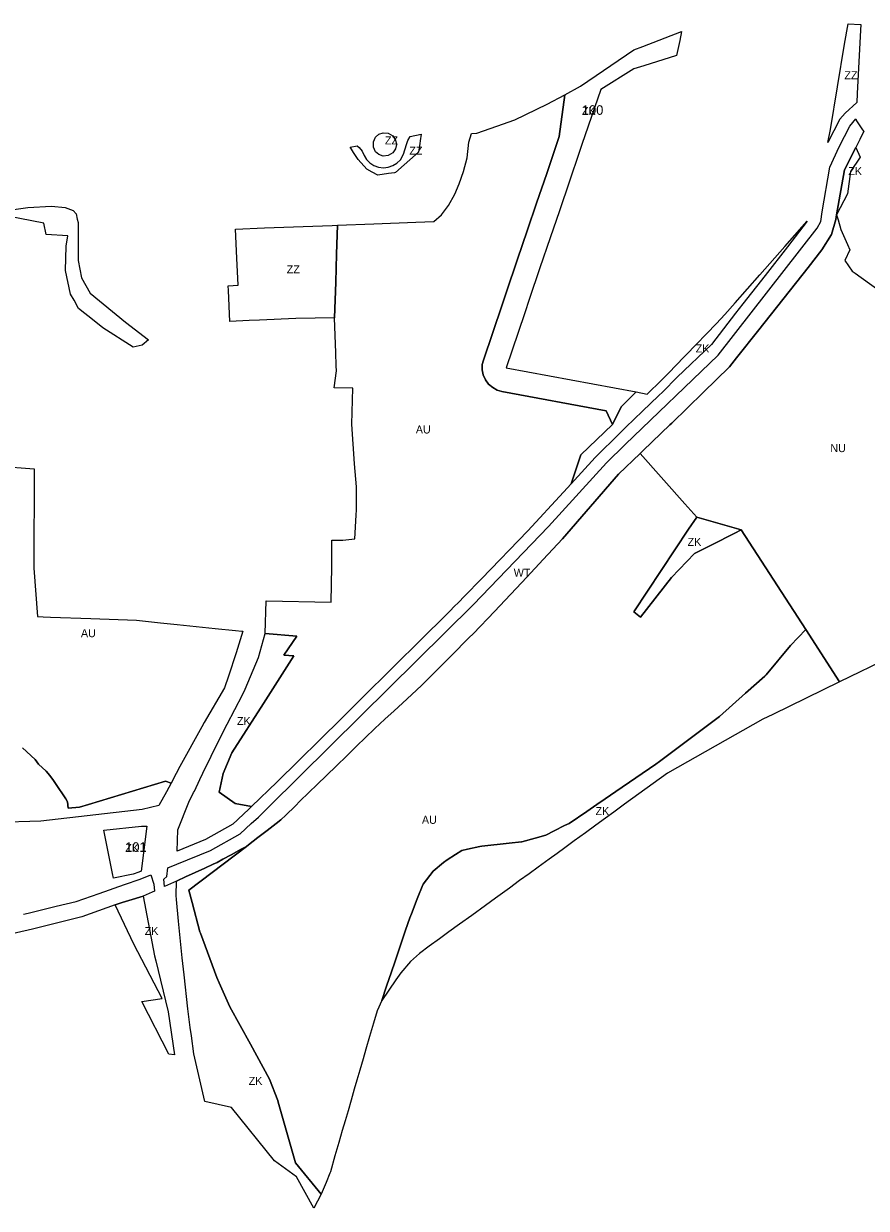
# Model space of a CAD drawing. Extents: x -535894 to -532834, y -1165802 to -1163647.
# Drawn here: x -534347 to -533821, y -1165557 to -1164817 of the extents above; entities that cross this region are included whole.
import ezdxf

# ---------------------------------------------------------------- set-up
doc = ezdxf.new("R2010")
doc.units = 0
for name, color, linetype in [('Vrstva 10', 7, 'Continuous'), ('Vrstva 16', 7, 'Continuous'), ('Vrstva 17', 7, 'Continuous'), ('Vrstva 19', 7, 'Continuous'), ('Vrstva 22', 7, 'Continuous'), ('Vrstva 4', 7, 'Continuous'), ('Vrstva 61', 7, 'Continuous')]:
    doc.layers.add(name, color=color, linetype=linetype)

msp = doc.modelspace()

# ---------------------------------------------------------------- linework, layer by layer
at = {"layer": 'Vrstva 10'}
for points in [[(-533843.57, -1164882.92), (-533834.83, -1164829.61), (-533832.622, -1164816.867), (-533824.861, -1164817.398), (-533824.726, -1164817.407), (-533824.567, -1164817.419), (-533824.9, -1164820.82), (-533826.93, -1164860.55), (-533827.206, -1164866.027), (-533834.51, -1164872.77), (-533837.807, -1164876.568), (-533845.178, -1164891.097)], [(-534119.58, -1164910.55), (-534126.18, -1164911.51), (-534129.86, -1164909.55), (-534133.17, -1164907.78), (-534138.57, -1164901.68), (-534141.45, -1164897.26), (-534142.74, -1164895.29), (-534143.59, -1164893.98), (-534139.15, -1164893.18), (-534137.85, -1164894.21), (-534136.17, -1164896.41), (-534136.05, -1164896.57), (-534134.79, -1164899.23), (-534133.26, -1164901.76), (-534131.19, -1164903.88), (-534128.69, -1164905.48), (-534125.82, -1164906.5), (-534122.74, -1164906.88), (-534119.83, -1164906.52), (-534117.01, -1164905.53), (-534114.35, -1164903.98), (-534112.2, -1164901.85), (-534110.31, -1164898.33), (-534108.42, -1164892.42), (-534108.18, -1164891.67), (-534107.59, -1164889.81), (-534106.11, -1164887.27), (-534099.32, -1164885.91), (-534099.92, -1164890.03), (-534100.15, -1164891.69), (-534100.95, -1164897.17), (-534115.28, -1164909.92), (-534115.91, -1164910.01)], [(-534129.089, -1164891.38), (-534129.089, -1164890.617), (-534127.712, -1164887.754), (-534125.618, -1164885.941), (-534123.001, -1164885.034), (-534119.833, -1164885.273), (-534116.941, -1164886.943), (-534115.564, -1164888.961), (-534115.15, -1164889.567), (-534114.627, -1164892.287), (-534115.15, -1164895.006), (-534116.941, -1164897.631), (-534119.833, -1164899.301), (-534123.001, -1164899.539), (-534125.618, -1164898.633), (-534127.712, -1164896.82), (-534129.089, -1164893.957)], [(-534151.409, -1164942.758), (-534151.409, -1164942.758), (-534152.01, -1164960.841), (-534152.589, -1164978.252), (-534153.33, -1165000.55), (-534177.53, -1165001), (-534200.18, -1165002.04), (-534206.706, -1165002.339), (-534218.76, -1165002.89), (-534219.6, -1164983.53), (-534219.73, -1164980.58), (-534213.51, -1164980.26), (-534214.43, -1164963.28), (-534215.272, -1164945.309), (-534197.15, -1164944.46), (-534154.72, -1164942.88)]]:
    msp.add_lwpolyline(points, close=True, dxfattribs=at)
msp.add_lwpolyline([(-534369.994, -1164935.234), (-534344.906, -1164931.755), (-534330.148, -1164930.912), (-534321.609, -1164931.634), (-534316.655, -1164933.547), (-534314.652, -1164935.656), (-534313.98, -1164938.937), (-534313.54, -1164941.084), (-534313.54, -1164953.57), (-534313.47, -1164964.73), (-534311.34, -1164975.55), (-534305.86, -1164985.22), (-534283.92, -1165003.31), (-534269.44, -1165014.34), (-534273.424, -1165017.68), (-534279.05, -1165019.05), (-534298, -1165006.84), (-534305.55, -1165000.89), (-534309.23, -1164997.99), (-534313.18, -1164994.87), (-534316.03, -1164989.68), (-534318.16, -1164985.83), (-534321.41, -1164971.12), (-534320.97, -1164955.95), (-534319.84, -1164949.47), (-534333.48, -1164948.48), (-534334.97, -1164941.39), (-534357.43, -1164937.18)], dxfattribs=at)
at = {"layer": 'Vrstva 16'}
for points in [[(-533834.91, -1164908.26), (-533827.81, -1164894.29), (-533825.11, -1164900.3), (-533831.01, -1164909.18), (-533832.91, -1164923.14), (-533839.74, -1164936.26)], [(-533990.612, -1165087.806), (-534005.544, -1165104.269), (-533999.48, -1165086.16), (-533979.67, -1165067.29), (-533974.3, -1165056.33), (-533964.89, -1165046.93), (-533958, -1165048.21), (-533949.192, -1165039.528), (-533943.27, -1165033.69), (-533941.12, -1165031.45), (-533933.76, -1165023.78), (-533914.87, -1165004.11), (-533909.61, -1164998.62), (-533903.09, -1164991.22), (-533887.6, -1164973.66), (-533872.1, -1164956.08), (-533858.16, -1164940.26), (-533870.466, -1164956.339), (-533884.317, -1164974.086), (-533898.225, -1164991.906), (-533902.835, -1164997.813), (-533917.983, -1165017.223), (-533939.32, -1165037.78), (-533948.251, -1165046.797), (-533950.892, -1165049.339), (-533960.954, -1165059.022), (-533971.32, -1165068.999), (-533974.832, -1165072.379)], [(-533899.27, -1165133.08), (-533903.4, -1165135.17), (-533917.7, -1165142.45), (-533922.67, -1165144.99), (-533928.42, -1165147.92), (-533942.82, -1165162.9), (-533962.19, -1165187.57), (-533966.39, -1165184.39), (-533932.156, -1165132.628), (-533927.15, -1165125.06)], [(-534251.577, -1165333.784), (-534251.27, -1165320.44), (-534244.31, -1165303.28), (-534241.33, -1165297.17), (-534240.88, -1165296.25), (-534237.36, -1165289.01), (-534235.49, -1165285.14), (-534225.18, -1165263.79), (-534220.39, -1165254.46), (-534210.89, -1165236.07), (-534209.06, -1165232.51), (-534200.78, -1165212.83), (-534196.74, -1165197.75), (-534176.94, -1165199.42), (-534185.07, -1165211.45), (-534178.75, -1165211.76), (-534197.75, -1165241.47), (-534217.42, -1165272.37), (-534222.91, -1165285.36), (-534225.42, -1165296.87), (-534215.31, -1165304.06), (-534205.1, -1165305.987), (-534206.827, -1165307.611), (-534213.437, -1165313.824), (-534213.981, -1165314.335), (-534216.742, -1165316.93), (-534233.955, -1165326.611)], [(-533837.937, -1165228.09), (-533879.59, -1165248.35), (-533885.93, -1165251.42), (-533945.33, -1165285.03), (-533972.2, -1165304.55), (-533978.9, -1165309.42), (-533984.1, -1165313.19), (-533990.15, -1165317.59), (-533996.63, -1165322.3), (-534003.61, -1165327.37), (-534009.54, -1165331.68), (-534014.32, -1165335.17), (-534019.31, -1165338.8), (-534026.18, -1165343.78), (-534031.82, -1165347.88), (-534037.71, -1165352.16), (-534044.14, -1165356.83), (-534052.73, -1165363.08), (-534059.04, -1165367.66), (-534067.65, -1165373.91), (-534075.22, -1165379.41), (-534081.89, -1165384.25), (-534087.82, -1165388.56), (-534094.23, -1165393.22), (-534100.32, -1165397.66), (-534105.93, -1165402.64), (-534112, -1165409.73), (-534115, -1165414.12), (-534119.41, -1165420.59), (-534123.86, -1165427.13), (-534120.771, -1165418.057), (-534117.758, -1165409.211), (-534115.724, -1165403.237), (-534111.863, -1165391.898), (-534108.906, -1165383.215), (-534106.3, -1165375.56), (-534105.277, -1165372.936), (-534101.626, -1165363.573), (-534098.22, -1165354.84), (-534097.973, -1165354.516), (-534091.65, -1165346.25), (-534085.262, -1165340.992), (-534083.06, -1165339.18), (-534077.737, -1165335.863), (-534073.72, -1165333.36), (-534070.381, -1165332.603), (-534062.61, -1165330.84), (-534061.335, -1165330.704), (-534044.246, -1165328.878), (-534036.59, -1165328.06), (-534036.334, -1165327.987), (-534027.934, -1165325.603), (-534021.44, -1165323.76), (-534016.244, -1165321.16), (-534009.645, -1165317.859), (-534006.79, -1165316.43), (-533995.833, -1165308.952), (-533989.599, -1165304.697), (-533984.271, -1165301.06), (-533977.619, -1165296.52), (-533952.74, -1165279.54), (-533950.278, -1165277.701), (-533912.83, -1165249.72), (-533896.579, -1165235.159), (-533884.619, -1165224.443), (-533883.79, -1165223.7), (-533868.63, -1165205.25), (-533859.04, -1165195.4)], [(-534240.38, -1165347.14), (-534234.4, -1165344.4), (-534229.05, -1165341.96), (-534226.73, -1165340.9), (-534223, -1165338.87), (-534217.81, -1165336.04), (-534211.58, -1165332.65), (-534208.23, -1165330.82), (-534244.32, -1165358.176), (-534242.299, -1165365.808), (-534237.43, -1165384.2), (-534237.131, -1165385.002), (-534226.8, -1165412.68), (-534225.304, -1165416.084), (-534218.71, -1165431.09), (-534205.89, -1165454.365), (-534193.89, -1165476.15), (-534188.83, -1165489.57), (-534188.526, -1165490.638), (-534177.746, -1165528.448), (-534161.64, -1165548.15), (-534166.28, -1165556.93), (-534177.14, -1165537.32), (-534190.83, -1165527.2), (-534217.59, -1165493.98), (-534234.3, -1165490.14), (-534241.22, -1165460.36), (-534242.7, -1165449.22), (-534243.4, -1165444.03), (-534244.98, -1165432.27), (-534247.31, -1165411.07), (-534248.48, -1165400.41), (-534250.69, -1165377.47), (-534251.99, -1165363.99), (-534252.23, -1165361.54), (-534252.01, -1165352.47), (-534251.58, -1165352.26), (-534246.5, -1165349.94)], [(-534281.74, -1165364.67), (-534272.9, -1165362.02), (-534265.72, -1165399.2), (-534264.94, -1165402.42), (-534262.04, -1165414.36), (-534257.19, -1165434.29), (-534253.34, -1165461.15), (-534256.73, -1165460.61), (-534273.58, -1165427.79), (-534260.88, -1165425.85), (-534278.69, -1165391.9), (-534290.38, -1165367.27), (-534285.88, -1165365.91)]]:
    msp.add_lwpolyline(points, close=True, dxfattribs=at)
msp.add_lwpolyline([(-534348.28, -1165269.23), (-534340.36, -1165276.59), (-534338.28, -1165279.56), (-534333.44, -1165283.8), (-534331.16, -1165286.47), (-534328.82, -1165289.63), (-534326.29, -1165293.35), (-534322.34, -1165299.19), (-534321.2, -1165301.18), (-534320.19, -1165302.94), (-534319.78, -1165307.01), (-534312.62, -1165306.37), (-534306.94, -1165304.65), (-534258.88, -1165290.11), (-534255.45, -1165291.38), (-534258.18, -1165296.74), (-534263.07, -1165305.2), (-534273.43, -1165307.68), (-534336.76, -1165315.12), (-534364.57, -1165315.97)], dxfattribs=at)
at = {"layer": 'Vrstva 17'}
for points in [[(-533960.78, -1164831.03), (-533936.53, -1164821.76), (-533937.75, -1164827.32), (-533939.824, -1164836.771), (-533960.22, -1164843.182), (-533966.45, -1164845.14), (-533986.98, -1164857.88), (-533998.79, -1164892.25), (-534000.56, -1164897.43), (-534006.6, -1164915.2), (-534012.88, -1164933.73), (-534018.61, -1164950.58), (-534025.02, -1164969.45), (-534031.7, -1164989.14), (-534034.52, -1164997.43), (-534038.74, -1165009.878), (-534046.172, -1165031.796), (-533964.89, -1165046.93), (-533974.3, -1165056.33), (-533979.67, -1165067.29), (-533983.719, -1165058.682), (-534048.917, -1165046.543), (-534051.748, -1165045.721), (-534054.541, -1165044.245), (-534057.072, -1165042.101), (-534059.114, -1165039.378), (-534060.49, -1165036.266), (-534061.122, -1165033.009), (-534061.045, -1165029.851), (-534060.377, -1165026.98), (-534048.723, -1164992.607), (-534045.903, -1164984.315), (-534039.224, -1164964.628), (-534032.812, -1164945.753), (-534027.084, -1164928.908), (-534020.803, -1164910.376), (-534012.983, -1164887.396), (-534009.46, -1164861.214), (-533999.79, -1164855.92), (-533966.36, -1164833.16)], [(-534274.043, -1165346.403), (-534275.59, -1165346.89), (-534279.12, -1165348.18), (-534291.425, -1165350.782), (-534292.023, -1165347.813), (-534297.487, -1165320.705), (-534273.89, -1165318.16), (-534270.61, -1165318.24)]]:
    msp.add_lwpolyline(points, close=True, dxfattribs=at)
at = {"layer": 'Vrstva 19'}
msp.add_lwpolyline([(-533806.07, -1165212.59), (-533837.937, -1165228.09), (-533859.04, -1165195.4), (-533899.27, -1165133.08), (-533927.15, -1165125.06), (-533934.45, -1165116.87), (-533962.53, -1165085.32), (-533960.64, -1165083.51), (-533943.82, -1165067.47), (-533942.64, -1165066.34), (-533923.15, -1165047.3), (-533906.69, -1165031.23), (-533902.3, -1165025.67), (-533888.41, -1165008.1), (-533857.58, -1164969.11), (-533848.9, -1164958.14), (-533842.95, -1164948.65), (-533840.25, -1164939.22), (-533839.74, -1164936.26), (-533838.84, -1164939.32), (-533837.05, -1164945.36), (-533833.05, -1164954.72), (-533831.57, -1164958.17), (-533834.67, -1164964.81), (-533830.03, -1164971.49), (-533828.25, -1164972.65), (-533784.18, -1165004.34)], dxfattribs=at)
at = {"layer": 'Vrstva 22'}
for points in [[(-534151.409, -1164942.758), (-534151.409, -1164942.758), (-534128.76, -1164941.92), (-534102.62, -1164940.95), (-534091.39, -1164940.53), (-534086.44, -1164936.35), (-534082.19, -1164930.46), (-534078.29, -1164923.33), (-534075.53, -1164917.01), (-534072.79, -1164909.21), (-534070.43, -1164900.65), (-534069.42, -1164890.86), (-534067.68, -1164885.4), (-534064.45, -1164885.27), (-534051.898, -1164880.919), (-534040.68, -1164877.03), (-534020.45, -1164867.23), (-534009.46, -1164861.214), (-534012.983, -1164887.396), (-534020.803, -1164910.376), (-534027.084, -1164928.908), (-534032.812, -1164945.753), (-534039.224, -1164964.628), (-534045.903, -1164984.315), (-534048.723, -1164992.607), (-534060.377, -1165026.98), (-534061.045, -1165029.851), (-534061.122, -1165033.009), (-534060.49, -1165036.266), (-534059.114, -1165039.378), (-534057.072, -1165042.101), (-534054.541, -1165044.245), (-534051.748, -1165045.721), (-534048.917, -1165046.543), (-533983.719, -1165058.682), (-533979.67, -1165067.29), (-533999.48, -1165086.16), (-534005.544, -1165104.269), (-534010.382, -1165109.604), (-534032.625, -1165133.636), (-534061.508, -1165163.605), (-534072.062, -1165174.555), (-534075.928, -1165178.389), (-534078.555, -1165180.995), (-534081.184, -1165183.602), (-534101.588, -1165203.839), (-534114.175, -1165216.322), (-534139.471, -1165241.41), (-534149.077, -1165250.937), (-534189.229, -1165290.586), (-534205.1, -1165305.987), (-534215.31, -1165304.06), (-534225.42, -1165296.87), (-534222.91, -1165285.36), (-534217.42, -1165272.37), (-534197.75, -1165241.47), (-534178.75, -1165211.76), (-534185.07, -1165211.45), (-534176.94, -1165199.42), (-534196.74, -1165197.75), (-534196.09, -1165177.34), (-534155.485, -1165178.292), (-534154.969, -1165156.285), (-534154.969, -1165139.562), (-534148.07, -1165139.43), (-534140.75, -1165138.6), (-534139.87, -1165123.82), (-534139.68, -1165120.52), (-534139.68, -1165106.21), (-534140.8, -1165091.86), (-534142.42, -1165067.13), (-534141.947, -1165044.615), (-534153.61, -1165044.37), (-534152.16, -1165033.67), (-534152.25, -1165030.59), (-534152.58, -1165022.25), (-534152.95, -1165011.58), (-534153.33, -1165000.55), (-534152.589, -1164978.252), (-534152.01, -1164960.841)], [(-533962.53, -1165085.32), (-533934.45, -1165116.87), (-533927.15, -1165125.06), (-533932.156, -1165132.628), (-533966.39, -1165184.39), (-533962.19, -1165187.57), (-533942.82, -1165162.9), (-533928.42, -1165147.92), (-533922.67, -1165144.99), (-533917.7, -1165142.45), (-533903.4, -1165135.17), (-533899.27, -1165133.08), (-533859.04, -1165195.4), (-533868.63, -1165205.25), (-533883.79, -1165223.7), (-533884.619, -1165224.443), (-533896.579, -1165235.159), (-533912.83, -1165249.72), (-533950.278, -1165277.701), (-533952.74, -1165279.54), (-533977.619, -1165296.52), (-533984.271, -1165301.06), (-533989.599, -1165304.697), (-533995.833, -1165308.952), (-534006.79, -1165316.43), (-534009.645, -1165317.859), (-534016.244, -1165321.16), (-534021.44, -1165323.76), (-534027.934, -1165325.603), (-534036.334, -1165327.987), (-534036.59, -1165328.06), (-534044.246, -1165328.878), (-534061.335, -1165330.704), (-534062.61, -1165330.84), (-534070.381, -1165332.603), (-534073.72, -1165333.36), (-534077.737, -1165335.863), (-534083.06, -1165339.18), (-534085.262, -1165340.992), (-534091.65, -1165346.25), (-534097.973, -1165354.516), (-534098.22, -1165354.84), (-534101.626, -1165363.573), (-534105.277, -1165372.936), (-534106.3, -1165375.56), (-534108.906, -1165383.215), (-534111.863, -1165391.898), (-534115.724, -1165403.237), (-534117.758, -1165409.211), (-534120.771, -1165418.057), (-534123.86, -1165427.13), (-534126.75, -1165433.55), (-534129.01, -1165441.31), (-534131.39, -1165449.51), (-534133.74, -1165457.61), (-534135.45, -1165463.49), (-534137.53, -1165470.62), (-534139.34, -1165476.85), (-534140.98, -1165482.5), (-534142.99, -1165489.42), (-534144.9, -1165495.99), (-534146.71, -1165502.23), (-534148.5, -1165508.42), (-534150.66, -1165515.85), (-534153.04, -1165524.07), (-534155.94, -1165534.08), (-534156.24, -1165535.07), (-534158.49, -1165540.9), (-534161.64, -1165548.15), (-534177.746, -1165528.448), (-534188.526, -1165490.638), (-534188.83, -1165489.57), (-534193.89, -1165476.15), (-534205.89, -1165454.365), (-534218.71, -1165431.09), (-534225.304, -1165416.084), (-534226.8, -1165412.68), (-534237.131, -1165385.002), (-534237.43, -1165384.2), (-534242.299, -1165365.808), (-534244.32, -1165358.176), (-534208.23, -1165330.82), (-534207.06, -1165329.91), (-534201.15, -1165325.32), (-534195.4, -1165320.86), (-534189.75, -1165316.48), (-534186.9, -1165314.27), (-534183.78, -1165311.24), (-534178, -1165305.62), (-534174.7, -1165302.41), (-534169.57, -1165297.42), (-534163.98, -1165291.99), (-534158.49, -1165286.65), (-534151.99, -1165280.33), (-534145.91, -1165274.41), (-534140, -1165268.66), (-534133.62, -1165262.47), (-534128.78, -1165257.75), (-534128.1, -1165257.13), (-534121.92, -1165251.44), (-534116.12, -1165246.09), (-534110.88, -1165241.27), (-534105.03, -1165235.88), (-534098.91, -1165230.23), (-534093.73, -1165225.02), (-534088.44, -1165219.7), (-534083.69, -1165214.91), (-534080.31, -1165211.51), (-534069.42, -1165200.54), (-534066.63, -1165197.75), (-534062.36, -1165193.44), (-534057.5, -1165188.56), (-534053.42, -1165184.18), (-534033.26, -1165162.58), (-534022.96, -1165151.54), (-534010.91, -1165138.64), (-533976.02, -1165098.2)]]:
    msp.add_lwpolyline(points, close=True, dxfattribs=at)
msp.add_lwpolyline([(-534362.94, -1165093.25), (-534340.945, -1165094.96), (-534341.17, -1165157.05), (-534338.8, -1165187.24), (-534335.39, -1165187.36), (-534330.752, -1165187.542), (-534305.54, -1165188.53), (-534277.01, -1165189.45), (-534261.966, -1165191.071), (-534251.58, -1165192.19), (-534227.96, -1165194.63), (-534215.09, -1165195.97), (-534211.25, -1165196.37), (-534210.61, -1165196.44), (-534214.76, -1165209.81), (-534219.65, -1165224.42), (-534222.12, -1165231.81), (-534234.65, -1165253.49), (-534236.16, -1165256.09), (-534249.84, -1165280.89), (-534252.19, -1165285.28), (-534255.45, -1165291.38), (-534258.88, -1165290.11), (-534306.94, -1165304.65), (-534312.62, -1165306.37), (-534319.78, -1165307.01), (-534320.19, -1165302.94), (-534321.2, -1165301.18), (-534322.34, -1165299.19), (-534326.29, -1165293.35), (-534328.82, -1165289.63), (-534331.16, -1165286.47), (-534333.44, -1165283.8), (-534338.28, -1165279.56), (-534340.36, -1165276.59), (-534348.28, -1165269.23)], dxfattribs=at)
at = {"layer": 'Vrstva 4'}
msp.add_lwpolyline([(-534229.05, -1165341.96), (-534234.4, -1165344.4), (-534240.38, -1165347.14), (-534246.5, -1165349.94), (-534251.58, -1165352.26), (-534252.01, -1165352.47), (-534259.48, -1165355.88), (-534259.96, -1165351.32), (-534257.97, -1165349.66), (-534257.49, -1165344.29), (-534251.77, -1165341.96), (-534230.69, -1165333.38), (-534212.27, -1165323.02), (-534205.31, -1165316.61), (-534200.89, -1165312.54), (-534194.29, -1165306.12), (-534136.8, -1165249.37), (-534066.72, -1165179.82), (-534019.59, -1165130.92), (-533983.52, -1165091.15), (-533971.79, -1165079.79), (-533913.79, -1165024.04), (-533851.83, -1164944.65), (-533849.69, -1164940.46), (-533848.679, -1164934.441), (-533843.98, -1164906.47), (-533838.18, -1164893.83), (-533831.54, -1164880.79), (-533827.73, -1164876.4), (-533827.39, -1164877.5), (-533823.63, -1164883.1), (-533822.83, -1164884.292), (-533825.17, -1164889.09), (-533825.28, -1164889.29), (-533827.81, -1164894.29), (-533834.91, -1164908.26), (-533839.74, -1164936.26), (-533840.25, -1164939.22), (-533842.95, -1164948.65), (-533848.9, -1164958.14), (-533857.58, -1164969.11), (-533888.41, -1165008.1), (-533902.3, -1165025.67), (-533906.69, -1165031.23), (-533923.15, -1165047.3), (-533942.64, -1165066.34), (-533943.82, -1165067.47), (-533960.64, -1165083.51), (-533962.53, -1165085.32), (-533976.02, -1165098.2), (-534010.91, -1165138.64), (-534022.96, -1165151.54), (-534033.26, -1165162.58), (-534053.42, -1165184.18), (-534057.5, -1165188.56), (-534062.36, -1165193.44), (-534066.63, -1165197.75), (-534069.42, -1165200.54), (-534080.31, -1165211.51), (-534083.69, -1165214.91), (-534088.44, -1165219.7), (-534093.73, -1165225.02), (-534098.91, -1165230.23), (-534105.03, -1165235.88), (-534110.88, -1165241.27), (-534116.12, -1165246.09), (-534121.92, -1165251.44), (-534128.1, -1165257.13), (-534128.78, -1165257.75), (-534133.62, -1165262.47), (-534140, -1165268.66), (-534145.91, -1165274.41), (-534151.99, -1165280.33), (-534158.49, -1165286.65), (-534163.98, -1165291.99), (-534169.57, -1165297.42), (-534174.7, -1165302.41), (-534178, -1165305.62), (-534183.78, -1165311.24), (-534186.9, -1165314.27), (-534189.75, -1165316.48), (-534195.4, -1165320.86), (-534201.15, -1165325.32), (-534207.06, -1165329.91), (-534208.23, -1165330.82), (-534211.58, -1165332.65), (-534217.81, -1165336.04), (-534223, -1165338.87), (-534226.73, -1165340.9)], close=True, dxfattribs=at)
msp.add_lwpolyline([(-534347.57, -1165373.21), (-534344.67, -1165372.49), (-534327.1, -1165368.26), (-534314.72, -1165365.27), (-534300.23, -1165360.21), (-534284.53, -1165354.73), (-534274.64, -1165351.27), (-534268.13, -1165348.62), (-534266.24, -1165354.33), (-534265.74, -1165358.75), (-534267.32, -1165359.47), (-534272.9, -1165362.02), (-534281.74, -1165364.67), (-534285.88, -1165365.91), (-534290.38, -1165367.27), (-534311.13, -1165374.91), (-534341.94, -1165382.62), (-534404.04, -1165396.72)], dxfattribs=at)

# ---------------------------------------------------------------- texts
at = {"layer": 'Vrstva 10'}
for p in [(-533834.8725, -1164851.5284), (-534121.858, -1164892.2865), (-534106.5974, -1164898.71)]:
    msp.add_text('ZZ', height=5, rotation=0, dxfattribs=at).set_placement(p)
msp.add_text('ZZ', height=5, dxfattribs=at).set_placement((-534183.1607, -1164972.824))
at = {"layer": 'Vrstva 16'}
for rotation, p in [(360, (-533832.425, -1164911.4735)), (359.9999999, (-533927.7602, -1165022.2645)), (359.9999999, (-533932.83, -1165143.0774)), (360, (-534214.2585, -1165254.9971)), (0, (-533990.3335, -1165311.265)), (0, (-534271.86, -1165386.1625)), (360, (-534206.935, -1165479.8375))]:
    msp.add_text('ZK', height=5, rotation=rotation, dxfattribs=at).set_placement(p)
at = {"layer": 'Vrstva 17'}
for rotation, p in [(0, (-533998.826, -1164873.8095)), (360, (-534284.0485, -1165334.2389))]:
    msp.add_text('ZK', height=5, rotation=rotation, dxfattribs=at).set_placement(p)
at = {"layer": 'Vrstva 19'}
msp.add_text('NU', height=5, rotation=360, dxfattribs=at).set_placement((-533843.67, -1165084.5038))
at = {"layer": 'Vrstva 22'}
for rotation, p in [(360, (-534102.545, -1165072.8676)), (0.0000001, (-534311.7029, -1165200.13)), (360, (-534098.7391, -1165316.735))]:
    msp.add_text('AU', height=5, rotation=rotation, dxfattribs=at).set_placement(p)
at = {"layer": 'Vrstva 4'}
msp.add_text('WT', height=5, rotation=360, dxfattribs=at).set_placement((-534041.395, -1165162.42))
at = {"layer": 'Vrstva 61'}
for s, p in [('100', (-533998.826, -1164873.8095)), ('101', (-534284.0485, -1165334.2389))]:
    msp.add_text(s, height=6, rotation=360, dxfattribs=at).set_placement(p)

doc.saveas('drawing.dxf')
